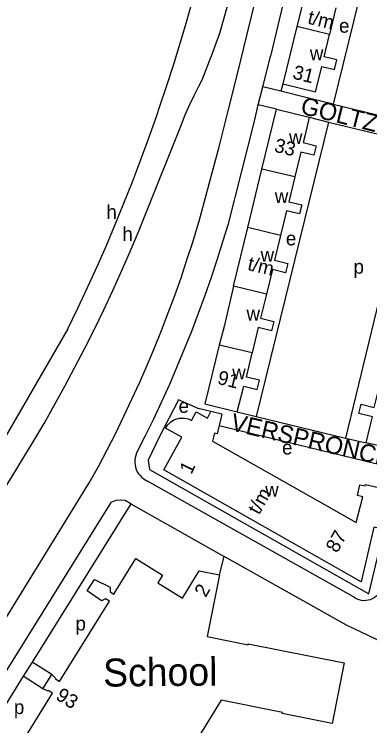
# Model space of a CAD drawing. Extents: x 162804 to 165059, y 381530 to 382901.
# Drawn here: x 162955.9 to 163057.6, y 382135.7 to 382339.3 of the extents above; entities that cross this region are included whole.
import ezdxf

# ---------------------------------------------------------------- set-up
doc = ezdxf.new("R2010")
doc.units = 0
for name, color, linetype in [('BLT_Basislijn', 7, 'Continuous'), ('BLT_Bebouwing', 7, 'Continuous'), ('BLT_Bebouwing_beschrifting', 7, 'Continuous'), ('BLT_Centroide', 7, 'Continuous'), ('BLT_Huisnummer_reeks', 7, 'Continuous'), ('BLT_Onderverdeling_panden', 7, 'Continuous'), ('BLT_Straatnaam', 7, 'Continuous'), ('BLT_Vlakafsluiter', 7, 'Continuous')]:
    doc.layers.add(name, color=color, linetype=linetype)

msp = doc.modelspace()

# ---------------------------------------------------------------- linework, layer by layer
at = {"layer": 'BLT_Basislijn'}
for p, q in [((163022.44, 382333.19), (163028.67, 382359)), ((163035.92, 382355.82), (163029.15, 382327.26)), ((163025.68, 382313.42), (163027.02, 382318.54)), ((163032.19, 382317.26), (163027.02, 382318.54)), ((163032.72, 382319.37), (163032.19, 382317.26)), ((163030.92, 382312.15), (163025.68, 382313.42)), ((163047.08, 382313.57), (163072.57, 382307.36)), ((163040.28, 382309.83), (163045.82, 382308.45)), ((162994.13, 382283.74), (163003.69, 382307.75)), ((163045.82, 382308.45), (163071.02, 382302.33)), ((163071.02, 382302.33), (163050.62, 382218)), ((163019.7, 382225.56), (163025.11, 382224.17)), ((163025.11, 382224.17), (163050.62, 382218)), ((163014.51, 382221.59), (163065.89, 382209.16)), ((163050.62, 382218), (163056.6, 382216.65)), ((163052.91, 382172.6), (162994.05, 382205.67)), ((162934.89, 382136.48), (162977.36, 382205.24)), ((162983.56, 382199.62), (162938.92, 382127.95)), ((162989.2, 382199.23), (162961, 382153.95)), ((162989.2, 382199.23), (163015.95, 382184.19)), ((163014.6, 382178.89), (163015.95, 382184.19)), ((162961, 382153.95), (162958.47, 382149.88)), ((162966.59, 382150.39), (162961, 382153.95)), ((162958.47, 382149.88), (162943.16, 382125.31)), ((162964.05, 382146.29), (162958.47, 382149.88))]:
    msp.add_line(p, q, dxfattribs=at)
for points in [[(163014.69, 382333.92), (163018.02, 382345.83), (163021.99, 382362.07), (163027.58, 382387.15)], [(162997.57, 382312.98), (162999.58, 382318.96), (163001.51, 382324.97), (163003.36, 382331), (163005.14, 382337.06), (163006.83, 382343.14), (163008.46, 382349.23), (163010, 382355.35), (163011.01, 382359.53)], [(163055.95, 382349.69), (163047.08, 382313.57)], [(163009.64, 382320.56), (163012.56, 382328.19), (163014.69, 382333.92)], [(163008.74, 382280.13), (163011.64, 382290.74), (163014.47, 382301.37), (163017.22, 382312.02), (163019.89, 382322.68), (163022.44, 382333.19)], [(163027.02, 382318.54), (163028.2, 382323.36), (163029.15, 382327.26)], [(163003.69, 382307.75), (163004.82, 382310.54), (163006.03, 382313.3), (163007.31, 382316.02), (163008.66, 382318.72), (163009.64, 382320.56)], [(163047.08, 382313.57), (163040.08, 382315.31), (163032.19, 382317.26)], [(163017.14, 382279.35), (163020.9, 382294), (163024.59, 382308.67), (163025.68, 382313.42)], [(162971.25, 382249.29), (162974.1, 382255.19), (162976.88, 382261.13), (162979.59, 382267.11), (162982.23, 382273.11), (162984.79, 382279.15), (162987.27, 382285.22), (162989.69, 382291.32), (162992.03, 382297.45), (162994.29, 382303.61), (162996.48, 382309.79), (162997.57, 382312.98)], [(163045.82, 382308.45), (163025.11, 382224.17)], [(162961.31, 382216.97), (162964.4, 382222.24), (162967.42, 382227.56), (162970.37, 382232.92), (162973.26, 382238.31), (162976.07, 382243.74), (162978.81, 382249.21), (162981.48, 382254.72), (162984.07, 382260.25), (162986.6, 382265.82), (162989.05, 382271.43), (162991.42, 382277.06), (162993.73, 382282.73), (162994.13, 382283.74)], [(162977.36, 382205.24), (162979.94, 382209.94), (162982.45, 382214.68), (162984.9, 382219.46), (162987.27, 382224.27), (162989.56, 382229.12), (162991.79, 382234), (162993.94, 382238.91), (162996.02, 382243.86), (162998.03, 382248.83), (162999.96, 382253.84), (163001.82, 382258.87), (163003.6, 382263.93), (163005.3, 382269.02), (163006.93, 382274.13), (163008.48, 382279.27), (163008.74, 382280.13)], [(162990.9, 382213.68), (162993.37, 382218.57), (162995.77, 382223.5), (162998.09, 382228.47), (163000.35, 382233.47), (163002.52, 382238.49), (163004.63, 382243.56), (163006.66, 382248.65), (163008.62, 382253.77), (163010.5, 382258.92), (163012.3, 382264.09), (163014.03, 382269.29), (163015.69, 382274.52), (163017.14, 382279.35)], [(163008.46, 382226.5), (163002.87, 382228.96), (162997.38, 382218.33)], [(163012.16, 382225.64), (163008.46, 382226.5)], [(162997.38, 382218.33), (162994.16, 382211.75), (162994.56, 382209.09), (163057.34, 382173.49), (163061.73, 382191.88)], [(162932.54, 382173.48), (162936.51, 382178.99), (162940.41, 382184.55), (162944.25, 382190.16), (162948.02, 382195.81), (162951.72, 382201.51), (162955.36, 382207.25), (162958.93, 382213.03), (162961.31, 382216.97)], [(162990.9, 382213.68), (162990.65, 382213.04), (162990.48, 382212.38), (162990.39, 382211.71), (162990.37, 382211.03), (162990.43, 382210.35), (162990.58, 382209.68), (162990.8, 382209.03), (162991.09, 382208.42), (162991.45, 382207.84), (162991.86, 382207.34)], [(162991.86, 382207.34), (162992.38, 382206.8), (162992.96, 382206.33), (162993.59, 382205.91), (162994.05, 382205.67)], [(162989.22, 382199.18), (162987.66, 382200.13), (162986.32, 382200.3), (162984.98, 382200.2), (162983.56, 382199.62)], [(163074.84, 382152.14), (163073.69, 382152.43), (163069.53, 382155.59), (163050.9, 382164.53), (163015.95, 382184.19)], [(163060.49, 382174.23), (163060.17, 382173.68), (163059.78, 382173.19), (163059.33, 382172.74), (163058.83, 382172.36), (163058.28, 382172.04), (163057.7, 382171.79), (163057.09, 382171.62), (163056.46, 382171.53), (163055.83, 382171.51), (163055.2, 382171.58), (163054.59, 382171.72), (163053.99, 382171.94), (163053.43, 382172.24), (163052.91, 382172.6)]]:
    msp.add_lwpolyline(points, dxfattribs=at)
at = {"layer": 'BLT_Bebouwing'}
for p, q in [((163041.06, 382353.32), (163036.75, 382335.77)), ((163047.93, 382341.09), (163046.06, 382333.48)), ((163036.75, 382335.77), (163032.72, 382319.37)), ((163044.5, 382327.12), (163046.06, 382333.48)), ((163048.18, 382326.24), (163044.5, 382327.12)), ((163047.52, 382323.45), (163048.18, 382326.24)), ((163043.26, 382321.94), (163043.84, 382324.33)), ((163043.84, 382324.33), (163047.52, 382323.45)), ((163042.06, 382317.08), (163043.26, 382321.94)), ((163032.72, 382319.37), (163042.06, 382317.08)), ((163026.76, 382295.02), (163030.92, 382312.15)), ((163030.92, 382312.15), (163040.28, 382309.83)), ((163022.69, 382278.28), (163026.76, 382295.02)), ((163018.61, 382261.47), (163022.69, 382278.28)), ((163012.64, 382217.11), (163044.68, 382199.01)), ((163065.87, 382214.41), (163056.6, 382216.65))]:
    msp.add_line(p, q, dxfattribs=at)
for points in [[(163040.28, 382309.83), (163039.07, 382304.83), (163038.52, 382302.56), (163042.21, 382301.67), (163041.56, 382298.96), (163037.85, 382299.85), (163036.13, 382292.75)], [(163036.13, 382292.75), (163034.42, 382285.65), (163038.14, 382284.74), (163037.52, 382282.18), (163033.78, 382283.09), (163032.07, 382276.01)], [(163032.07, 382276.01), (163030.36, 382268.93), (163034.12, 382268.02), (163033.47, 382265.36), (163029.72, 382266.26), (163028.02, 382259.2)], [(163018.61, 382261.47), (163015.96, 382250), (163014.52, 382244.66)], [(163028.02, 382259.2), (163026.35, 382252.3), (163030.13, 382251.39), (163029.47, 382248.73), (163025.71, 382249.64), (163023.95, 382242.38)], [(163014.52, 382244.66), (163010.44, 382227.83), (163019.7, 382225.56)], [(163019.7, 382225.56), (163021.52, 382232.88), (163025.4, 382231.92), (163026.04, 382234.58), (163022.29, 382235.49), (163023.95, 382242.38)], [(163056.6, 382216.65), (163057.68, 382221.44), (163058.38, 382224.09), (163054.45, 382225.06), (163055.1, 382227.7), (163058.88, 382226.77), (163060.56, 382233.61)], [(162999.19, 382220.9), (162999.86, 382221.86), (163000.63, 382222.61), (163001.51, 382223.21), (163003.02, 382223.69), (163004.61, 382223.77), (163005.65, 382223.53), (163006.61, 382223.09), (163007.95, 382225.51), (163011.17, 382223.72), (163012.16, 382225.64)], [(163015.25, 382224.9), (163012.16, 382225.64)], [(163015.25, 382224.9), (163014.51, 382221.59)], [(163055.14, 382176.95), (162998.63, 382208.97), (163003.86, 382218.27), (162999.19, 382220.9)], [(163014.51, 382221.59), (163013.98, 382219.24), (163013.2, 382219.42), (163012.64, 382217.11)], [(163044.68, 382199.01), (163053.72, 382193.9), (163055.59, 382201.21), (163054.05, 382201.57), (163054.77, 382204.67), (163056.3, 382204.36), (163056.39, 382204.71), (163064.21, 382202.92)], [(163061.73, 382191.88), (163058.74, 382192.55), (163055.14, 382176.95)], [(162966.59, 382150.39), (162967.67, 382149.32), (162967.6, 382149.2), (162968.87, 382148.42), (162983.09, 382171.39), (162982.02, 382172.06), (162980.85, 382171.43), (162976.77, 382174.34), (162978.8, 382177.61), (162983.34, 382175.33), (162983.3, 382174.08), (162984.36, 382173.42), (162990.63, 382183.56)], [(162990.63, 382183.56), (162998.33, 382178.85), (162996.95, 382176.61), (163003.99, 382172.26), (163008.81, 382180.06)], [(163008.81, 382180.06), (163014.6, 382178.89)], [(163014.6, 382178.89), (163011.07, 382161.23), (163022.77, 382158.87), (163022.84, 382159.19), (163050.3, 382153.71), (163046.79, 382136.34), (163032.5, 382139.24), (163032.61, 382139.53), (163015.07, 382143.06), (163007.93, 382131.41)], [(162964.05, 382146.29), (162966.59, 382150.39)], [(162956.2, 382127.87), (162966.81, 382145.03), (162965.6, 382145.78), (162965.51, 382145.62), (162964.05, 382146.29)]]:
    msp.add_lwpolyline(points, dxfattribs=at)
at = {"layer": 'BLT_Onderverdeling_panden'}
for p, q in [((163046.06, 382333.48), (163036.75, 382335.77)), ((163036.13, 382292.75), (163026.76, 382295.02)), ((163032.07, 382276.01), (163022.69, 382278.28)), ((163028.02, 382259.2), (163018.61, 382261.47)), ((163023.95, 382242.38), (163014.52, 382244.66))]:
    msp.add_line(p, q, dxfattribs=at)
at = {"layer": 'BLT_Vlakafsluiter'}
msp.add_line((162971.25, 382249.29), (162941.77, 382198.77), dxfattribs=at)

# ---------------------------------------------------------------- texts
at = {"layer": 'BLT_Bebouwing_beschrifting'}
msp.add_text('School', height=8, rotation=0.5918, dxfattribs=at).set_placement((162981.34, 382146.91))
at = {"layer": 'BLT_Centroide'}
for s, p in [('e', (163048.81, 382334.02)), ('w', (163040.45, 382326.16)), ('w', (163034.48, 382302.2)), ('w', (163030.42, 382285.27)), ('h', (162982.24, 382280.72)), ('h', (162986.81, 382274.43)), ('e', (163033.6, 382273.17)), ('w', (163026.36, 382268.48)), ('p', (163052.95, 382265.07)), ('w', (163022.33, 382251.67)), ('w', (163018.23, 382234.83)), ('e', (163002.9, 382225.24)), ('e', (163032.5, 382213.34)), ('w', (163027.67, 382201.28)), ('p', (162973.4, 382162.98)), ('p', (162955.79, 382139.06))]:
    msp.add_text(s, height=4, dxfattribs=at).set_placement(p)
at = {"layer": 'BLT_Huisnummer_reeks'}
for s, rotation, p in [('t/m', 346.1971, (163039.59, 382336.67)), ('31', 346.1993, (163035.31, 382320.94)), ('33', 346.4058, (163030.03, 382300.02)), ('t/m', 346.406, (163022.4, 382266.19)), ('91', 346.4091, (163013.79, 382233.57)), ('1', 63.907, (163006.52, 382207.44)), ('t/m', 60.5301, (163025.91, 382195.86)), ('87', 60.5301, (163048.24, 382184.94)), ('2', 61.2499, (163010.69, 382172.24)), ('93', 328.2499, (162967.48, 382143.47))]:
    msp.add_text(s, height=4, rotation=rotation, dxfattribs=at).set_placement(p)
at = {"layer": 'BLT_Straatnaam'}
for s, height, rotation, p in [('GOLTZIUSPAD', 4.9999, 346.0834, (163037.51, 382310.92)), ('VERSPRONCKPAD', 5, 347.0007, (163017.5, 382220.31))]:
    msp.add_text(s, height=height, rotation=rotation, dxfattribs=at).set_placement(p)

doc.saveas('drawing.dxf')
